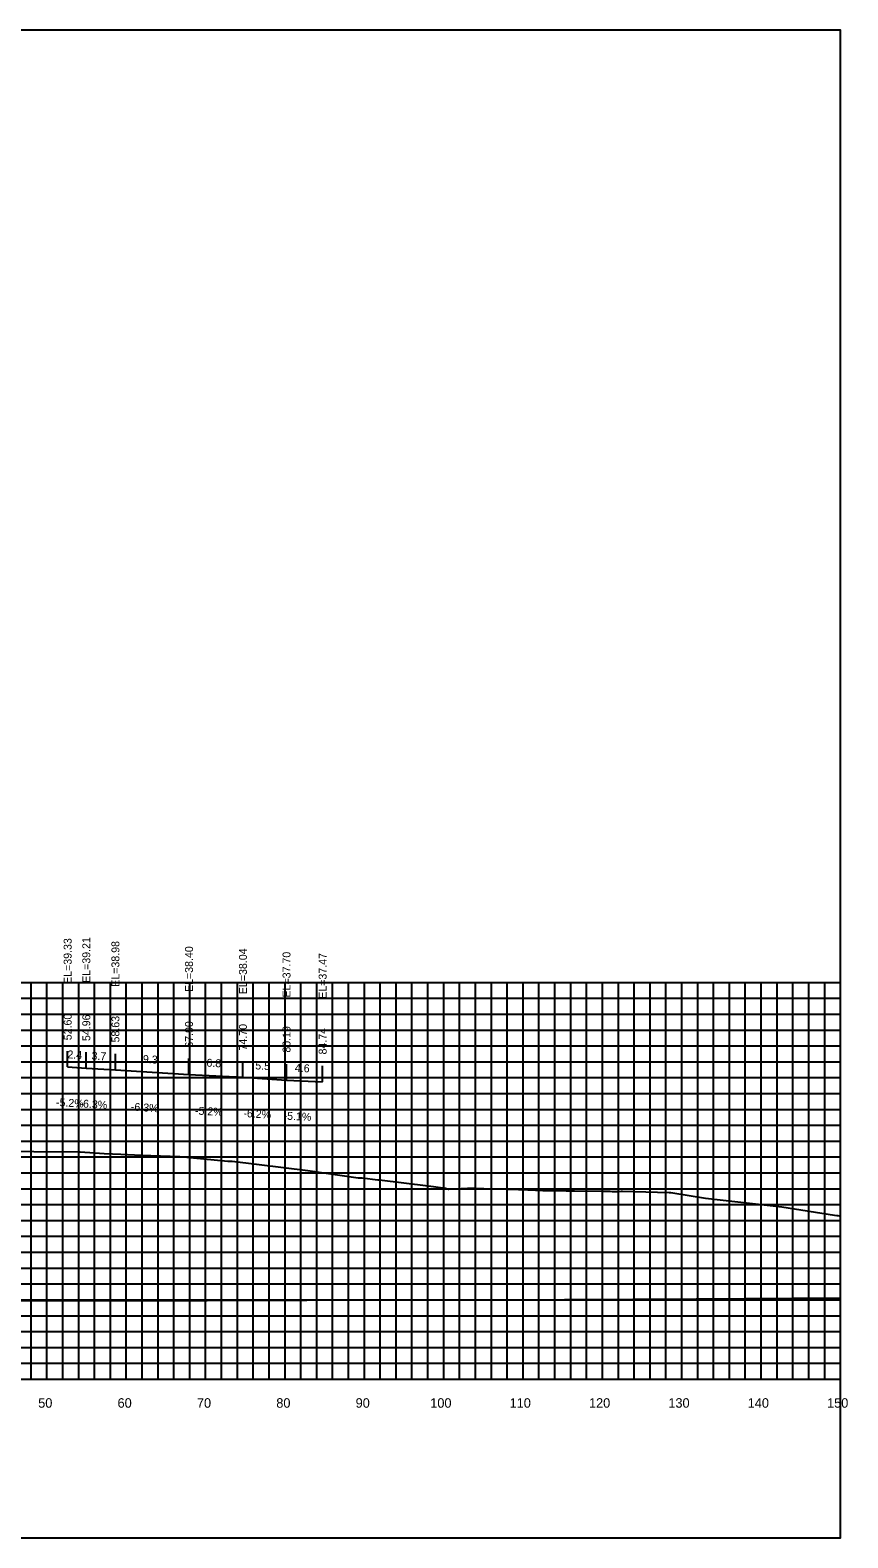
# Model space of a CAD drawing. Extents: x 1800880 to 1818864, y 245271 to 250560.
# Drawn here: x 1811146.7 to 1811249.7, y 247228 to 247418 of the extents above; entities that cross this region are included whole.
import ezdxf

# ---------------------------------------------------------------- set-up
doc = ezdxf.new("R2010")
doc.units = 0
for name, color, linetype in [('ANNO-TXT', 7, 'Continuous'), ('CL-CNST', 7, 'Continuous'), ('DESIGN - DRAINAGE - Bridges', 7, 'Continuous'), ('Level 37', 7, 'Continuous'), ('Level 46', 7, 'Continuous'), ('Level 62', 7, 'Continuous'), ('SHT-BDR', 7, 'Continuous')]:
    doc.layers.add(name, color=color, linetype=linetype)

msp = doc.modelspace()

# ---------------------------------------------------------------- linework, layer by layer
at = {"layer": 'CL-CNST'}
msp.add_lwpolyline([(1811141.49, 247276.68), (1811152.8, 247276.58), (1811152.96, 247276.58), (1811153.01, 247276.58), (1811156.01, 247276.4), (1811158.14, 247276.3), (1811160.69, 247276.18), (1811165.57, 247276.03), (1811171.62, 247275.44), (1811171.95, 247275.44), (1811172.17, 247275.44), (1811181.67, 247274.24), (1811188.01, 247273.31), (1811188.17, 247273.31), (1811188.52, 247273.31), (1811190.49, 247273.07), (1811190.7, 247273.05), (1811196.83, 247272.32), (1811196.89, 247272.31), (1811199.04, 247272.02), (1811199.4, 247271.89), (1811199.47, 247271.89), (1811201.81, 247272.01), (1811201.85, 247272.01), (1811201.98, 247272.01), (1811202.03, 247272.02), (1811202.06, 247272.02), (1811202.06, 247272.02), (1811202.06, 247272.02), (1811202.06, 247272.02), (1811202.06, 247272.02), (1811202.06, 247272.02), (1811202.07, 247272.02), (1811202.07, 247272.02), (1811202.07, 247272.02), (1811202.07, 247272.02), (1811202.08, 247272.02), (1811202.08, 247272.02), (1811202.09, 247272.03), (1811202.1, 247272.03), (1811202.12, 247272.03), (1811202.15, 247272.03), (1811202.21, 247272.03), (1811202.42, 247272.03), (1811202.67, 247272.03), (1811205.1, 247271.95), (1811208.24, 247271.84), (1811209.39, 247271.8), (1811211.31, 247271.74), (1811211.38, 247271.74), (1811211.82, 247271.73), (1811214.24, 247271.7), (1811215.28, 247271.69), (1811218.76, 247271.66), (1811219.04, 247271.66), (1811219.09, 247271.66), (1811219.78, 247271.63), (1811220.03, 247271.61), (1811220.17, 247271.61), (1811220.25, 247271.6), (1811220.72, 247271.59), (1811221.15, 247271.63), (1811221.2, 247271.64), (1811221.32, 247271.64), (1811227.2, 247271.48), (1811227.41, 247271.47), (1811231.79, 247270.76), (1811241.43, 247269.66), (1811248.06, 247268.6), (1811248.36, 247268.56), (1811248.47, 247268.56), (1811248.81, 247268.51)], dxfattribs=at)
at = {"layer": 'DESIGN - DRAINAGE - Bridges'}
for p, q in [((1811248.81, 247247.95), (1811248.81, 247297.95)), ((1811248.87, 247297.95), (1811248.81, 247297.95)), ((1811248.87, 247287.95), (1811248.81, 247287.95)), ((1811248.87, 247277.95), (1811248.81, 247277.95)), ((1811248.87, 247267.95), (1811248.81, 247267.95)), ((1811248.87, 247257.95), (1811248.81, 247257.95)), ((1810948.81, 247247.95), (1811248.81, 247247.95)), ((1811148.81, 247247.89), (1811148.81, 247247.95)), ((1811158.81, 247247.89), (1811158.81, 247247.95)), ((1811168.81, 247247.89), (1811168.81, 247247.95)), ((1811178.81, 247247.89), (1811178.81, 247247.95)), ((1811188.81, 247247.89), (1811188.81, 247247.95)), ((1811198.81, 247247.89), (1811198.81, 247247.95)), ((1811208.81, 247247.89), (1811208.81, 247247.95)), ((1811218.81, 247247.89), (1811218.81, 247247.95)), ((1811228.81, 247247.89), (1811228.81, 247247.95)), ((1811238.81, 247247.89), (1811238.81, 247247.95)), ((1811248.81, 247247.89), (1811248.81, 247247.95)), ((1811248.87, 247247.95), (1811248.81, 247247.95))]:
    msp.add_line(p, q, dxfattribs=at)
at = {"layer": 'Level 37'}
for p, q in [((1811151.42, 247287.29), (1811151.42, 247289.29)), ((1811153.77, 247287.16), (1811153.77, 247289.16)), ((1811157.44, 247286.93), (1811157.44, 247288.93)), ((1811166.71, 247286.35), (1811166.71, 247288.35)), ((1811173.51, 247286), (1811173.51, 247288)), ((1811179, 247285.65), (1811179, 247287.65)), ((1811183.55, 247285.42), (1811183.55, 247287.42))]:
    msp.add_line(p, q, dxfattribs=at)
msp.add_lwpolyline([(1810948.81, 247227.95), (1811248.81, 247227.95), (1811248.81, 247417.95), (1810948.81, 247417.95)], close=True, dxfattribs=at)
at = {"layer": 'Level 46'}
for p, q in [((1810948.81, 247297.95), (1811248.81, 247297.95)), ((1811146.81, 247247.95), (1811146.81, 247297.95)), ((1811148.81, 247247.95), (1811148.81, 247297.95)), ((1811150.81, 247247.95), (1811150.81, 247297.95)), ((1811152.81, 247247.95), (1811152.81, 247297.95)), ((1811154.81, 247247.95), (1811154.81, 247297.95)), ((1811156.81, 247247.95), (1811156.81, 247297.95)), ((1811158.81, 247247.95), (1811158.81, 247297.95)), ((1811160.81, 247247.95), (1811160.81, 247297.95)), ((1811162.81, 247247.95), (1811162.81, 247297.95)), ((1811164.81, 247247.95), (1811164.81, 247297.95)), ((1811166.81, 247247.95), (1811166.81, 247297.95)), ((1811168.81, 247247.95), (1811168.81, 247297.95)), ((1811170.81, 247247.95), (1811170.81, 247297.95)), ((1811172.81, 247247.95), (1811172.81, 247297.95)), ((1811174.81, 247247.95), (1811174.81, 247297.95)), ((1811176.81, 247247.95), (1811176.81, 247297.95)), ((1811178.81, 247247.95), (1811178.81, 247297.95)), ((1811180.81, 247247.95), (1811180.81, 247297.95)), ((1811182.81, 247247.95), (1811182.81, 247297.95)), ((1811184.81, 247247.95), (1811184.81, 247297.95)), ((1811186.81, 247247.95), (1811186.81, 247297.95)), ((1811188.81, 247247.95), (1811188.81, 247297.95)), ((1811190.81, 247247.95), (1811190.81, 247297.95)), ((1811192.81, 247247.95), (1811192.81, 247297.95)), ((1811194.81, 247247.95), (1811194.81, 247297.95)), ((1811196.81, 247247.95), (1811196.81, 247297.95)), ((1811198.81, 247247.95), (1811198.81, 247297.95)), ((1811200.81, 247247.95), (1811200.81, 247297.95)), ((1811202.81, 247247.95), (1811202.81, 247297.95)), ((1811204.81, 247247.95), (1811204.81, 247297.95)), ((1811206.81, 247247.95), (1811206.81, 247297.95)), ((1811208.81, 247247.95), (1811208.81, 247297.95)), ((1811210.81, 247247.95), (1811210.81, 247297.95)), ((1811212.81, 247247.95), (1811212.81, 247297.95)), ((1811214.81, 247247.95), (1811214.81, 247297.95)), ((1811216.81, 247247.95), (1811216.81, 247297.95)), ((1811218.81, 247247.95), (1811218.81, 247297.95)), ((1811220.81, 247247.95), (1811220.81, 247297.95)), ((1811222.81, 247247.95), (1811222.81, 247297.95)), ((1811224.81, 247247.95), (1811224.81, 247297.95)), ((1811226.81, 247247.95), (1811226.81, 247297.95)), ((1811228.81, 247247.95), (1811228.81, 247297.95)), ((1811230.81, 247247.95), (1811230.81, 247297.95)), ((1811232.81, 247247.95), (1811232.81, 247297.95)), ((1811234.81, 247247.95), (1811234.81, 247297.95)), ((1811236.81, 247247.95), (1811236.81, 247297.95)), ((1811238.81, 247247.95), (1811238.81, 247297.95)), ((1811240.81, 247247.95), (1811240.81, 247297.95)), ((1811242.81, 247247.95), (1811242.81, 247297.95)), ((1811244.81, 247247.95), (1811244.81, 247297.95)), ((1811246.81, 247247.95), (1811246.81, 247297.95)), ((1811248.81, 247247.95), (1811248.81, 247297.95)), ((1810948.81, 247295.95), (1811248.81, 247295.95)), ((1810948.81, 247293.95), (1811248.81, 247293.95)), ((1810948.81, 247291.95), (1811248.81, 247291.95)), ((1810948.81, 247289.95), (1811248.81, 247289.95)), ((1810948.81, 247287.95), (1811248.81, 247287.95)), ((1810948.81, 247285.95), (1811248.81, 247285.95)), ((1810948.81, 247283.95), (1811248.81, 247283.95)), ((1810948.81, 247281.95), (1811248.81, 247281.95)), ((1810948.81, 247279.95), (1811248.81, 247279.95)), ((1810948.81, 247277.95), (1811248.81, 247277.95)), ((1810948.81, 247275.95), (1811248.81, 247275.95)), ((1810948.81, 247273.95), (1811248.81, 247273.95)), ((1810948.81, 247271.95), (1811248.81, 247271.95)), ((1810948.81, 247269.95), (1811248.81, 247269.95)), ((1810948.81, 247267.95), (1811248.81, 247267.95)), ((1810948.81, 247265.95), (1811248.81, 247265.95)), ((1810948.81, 247263.95), (1811248.81, 247263.95)), ((1810948.81, 247261.95), (1811248.81, 247261.95)), ((1810948.81, 247259.95), (1811248.81, 247259.95)), ((1810948.81, 247257.95), (1811248.81, 247257.95)), ((1810948.81, 247255.95), (1811248.81, 247255.95)), ((1810948.81, 247253.95), (1811248.81, 247253.95)), ((1810948.81, 247251.95), (1811248.81, 247251.95)), ((1810948.81, 247249.95), (1811248.81, 247249.95)), ((1810948.81, 247247.95), (1811248.81, 247247.95))]:
    msp.add_line(p, q, dxfattribs=at)
at = {"layer": 'Level 62'}
for points in [[(1811151.42, 247287.29), (1811153.77, 247287.16), (1811157.44, 247286.93), (1811166.71, 247286.35), (1811173.51, 247286), (1811179, 247285.65), (1811183.55, 247285.42)], [(1810948.81, 247259.24), (1810954.95, 247259.18), (1810974.72, 247258.74), (1810987.53, 247258.64), (1811002.47, 247258.45), (1811018.64, 247258.35), (1811030.23, 247258.24), (1811048.88, 247258.14), (1811057.98, 247258.08), (1811078.53, 247258.01), (1811085.74, 247257.94), (1811107.79, 247257.9), (1811113.49, 247257.87), (1811136.77, 247257.87), (1811141.25, 247257.83), (1811165.53, 247257.87), (1811169, 247257.85), (1811194.14, 247257.93), (1811196.76, 247257.92), (1811222.62, 247258.04), (1811224.51, 247258.04), (1811248.81, 247258.18)]]:
    msp.add_lwpolyline(points, dxfattribs=at)

# ---------------------------------------------------------------- texts
for s, p in [('50', (1811147.71, 247244.35)), ('60', (1811157.71, 247244.35)), ('70', (1811167.71, 247244.35)), ('80', (1811177.71, 247244.35)), ('90', (1811187.71, 247244.35)), ('100', (1811197.11, 247244.35)), ('110', (1811207.11, 247244.35)), ('120', (1811217.11, 247244.35)), ('130', (1811227.11, 247244.35)), ('140', (1811237.11, 247244.35)), ('150', (1811247.11, 247244.35))]:
    msp.add_text(s, height=1.2).set_placement(p)
at = {"layer": 'ANNO-TXT'}
for s, rotation, p in [('2.4', 357.0072, (1811151.37, 247288.39)), ('3.7', 356.4036, (1811154.4, 247288.23)), ('9.3', 356.4036, (1811160.87, 247287.82)), ('6.8', 357.0406, (1811168.89, 247287.34)), ('5.5', 356.4278, (1811175.04, 247287)), ('4.6', 357.0558, (1811180.03, 247286.7)), ('-5.2%', 357.0072, (1811149.93, 247282.36)), ('-6.3%', 356.4036, (1811152.89, 247282.21)), ('-6.3%', 356.4036, (1811159.36, 247281.8)), ('-5.2%', 357.0406, (1811167.45, 247281.3)), ('-6.2%', 356.4278, (1811173.54, 247280.99)), ('-5.1%', 357.0558, (1811178.61, 247280.67))]:
    msp.add_text(s, height=1, rotation=rotation, dxfattribs=at).set_placement(p)
at = {"layer": 'SHT-BDR'}
for s, p in [('EL=39.33', (1811151.92, 247297.76)), ('EL=39.21', (1811154.27, 247297.89)), ('EL=38.98', (1811157.94, 247297.4)), ('EL=38.40', (1811167.21, 247296.74)), ('EL=38.04', (1811174.01, 247296.47)), ('EL=37.70', (1811179.5, 247296.05)), ('EL=37.47', (1811184.05, 247295.89)), ('52.60', (1811151.92, 247290.66)), ('54.96', (1811154.27, 247290.56)), ('58.63', (1811157.94, 247290.38)), ('67.90', (1811167.21, 247289.72)), ('74.70', (1811174.01, 247289.37)), ('80.19', (1811179.5, 247289.1)), ('84.74', (1811184.05, 247288.87))]:
    msp.add_text(s, height=1, rotation=90, dxfattribs=at).set_placement(p)

doc.saveas('drawing.dxf')
